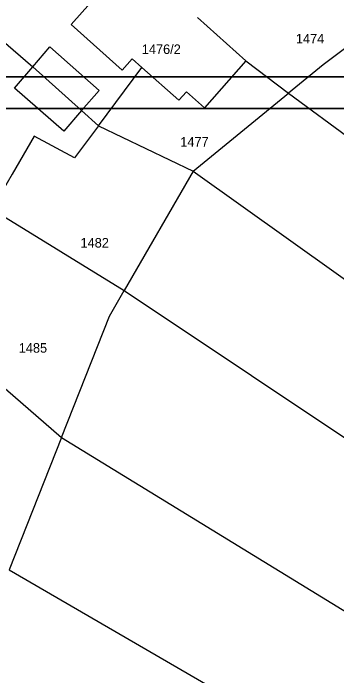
# Model space of a CAD drawing. Extents: x -601580 to 4, y -1204314 to 4.
# Drawn here: x -598853.3 to -598827.9, y -1203943.9 to -1203891.8 of the extents above; entities that cross this region are included whole.
import ezdxf

# ---------------------------------------------------------------- set-up
doc = ezdxf.new("R2010")
doc.units = 0
for name, color, linetype in [('00-KN-HRANICE PARCEL', 7, 'Continuous'), ('00-KN-PARC. CISLA', 7, 'Continuous'), ('00-KN-VNITRNI KRESBA', 7, 'Continuous'), ('00-RAZÍTKO', 7, 'Continuous')]:
    doc.layers.add(name, color=color, linetype=linetype)

msp = doc.modelspace()

# ---------------------------------------------------------------- linework, layer by layer
for points in [[(-598795.141, -1204045.311), (-598795.141, -1203896.811), (-599005.141, -1203896.811), (-599005.141, -1204045.311)], [(-598797.641, -1204042.811), (-598797.641, -1203899.311), (-599002.641, -1203899.311), (-599002.641, -1204042.811)]]:
    msp.add_lwpolyline(points, close=True)
for points in [[(-598900.191, -1204042.811), (-598900.191, -1204045.311), (-598795.141, -1204045.311), (-598795.141, -1203896.811), (-598900.191, -1203896.811), (-598900.191, -1203899.311)], [(-598897.691, -1204042.811), (-598797.641, -1204042.811), (-598797.641, -1203899.311), (-598897.691, -1203899.311)]]:
    msp.add_lwpolyline(points)
at = {"layer": '00-KN-HRANICE PARCEL'}
for p, q in [((-598838.811, -1203892.159), (-598835.011, -1203895.569)), ((-598835.011, -1203895.569), (-598831.661, -1203898.109)), ((-598846.611, -1203900.659), (-598843.191, -1203896.079)), ((-598839.141, -1203904.219), (-598831.661, -1203898.109)), ((-598831.661, -1203898.109), (-598778.841, -1203936.669)), ((-598846.611, -1203900.659), (-598839.141, -1203904.219)), ((-598839.141, -1203904.219), (-598844.571, -1203913.599)), ((-598854.991, -1203907.199), (-598844.571, -1203913.599)), ((-598859.991, -1203916.109), (-598849.501, -1203925.149)), ((-598849.501, -1203925.149), (-598853.621, -1203935.559))]:
    msp.add_line(p, q, dxfattribs=at)
for points in [[(-598863.941, -1203885.569), (-598856.251, -1203892.169), (-598851.771, -1203896.019)], [(-598843.191, -1203896.079), (-598843.941, -1203895.389), (-598844.731, -1203896.289), (-598848.761, -1203892.709), (-598846.571, -1203890.249), (-598847.351, -1203889.549), (-598844.901, -1203886.789)], [(-598825.061, -1203892.989), (-598828.931, -1203895.879), (-598831.661, -1203898.109)], [(-598835.011, -1203895.569), (-598838.261, -1203899.249), (-598839.681, -1203897.989), (-598840.281, -1203898.659), (-598843.191, -1203896.079)], [(-598851.771, -1203896.019), (-598847.931, -1203899.469), (-598846.611, -1203900.659)], [(-598846.611, -1203900.659), (-598848.501, -1203903.189), (-598851.671, -1203901.489)], [(-598851.671, -1203901.489), (-598853.401, -1203904.459), (-598854.991, -1203907.199)], [(-598839.141, -1203904.219), (-598786.271, -1203941.879), (-598785.311, -1203942.529)], [(-598849.501, -1203925.149), (-598845.741, -1203915.629), (-598844.571, -1203913.599)], [(-598844.571, -1203913.599), (-598794.321, -1203947.099), (-598792.031, -1203948.609)], [(-598849.501, -1203925.149), (-598803.711, -1203953.189), (-598789.701, -1203961.229)], [(-598853.621, -1203935.559), (-598812.931, -1203959.159), (-598806.131, -1203963.139)]]:
    msp.add_lwpolyline(points, dxfattribs=at)
at = {"layer": '00-KN-VNITRNI KRESBA'}
for p, q in [((-598851.771, -1203896.019), (-598850.431, -1203894.469)), ((-598850.431, -1203894.469), (-598846.561, -1203897.879)), ((-598853.221, -1203897.709), (-598851.771, -1203896.019)), ((-598849.331, -1203901.089), (-598853.221, -1203897.709)), ((-598846.561, -1203897.879), (-598847.931, -1203899.469)), ((-598847.931, -1203899.469), (-598849.331, -1203901.089))]:
    msp.add_line(p, q, dxfattribs=at)
at = {"layer": '00-RAZÍTKO'}
for points in [[(-599005.242, -1203896.811), (-598795.141, -1203896.811), (-598795.141, -1204045.311), (-599005.242, -1204045.311)], [(-599005.242, -1203899.311), (-598797.641, -1203899.311), (-598797.641, -1204042.811), (-599005.242, -1204042.811)]]:
    msp.add_lwpolyline(points, dxfattribs=at)

# ---------------------------------------------------------------- texts
at = {"layer": '00-KN-PARC. CISLA'}
for s, p in [('1474', (-598831.066, -1203894.189)), ('1476/2', (-598843.192, -1203895.019)), ('1477', (-598840.166, -1203902.299)), ('1482', (-598848.016, -1203910.229)), ('1485', (-598852.876, -1203918.489))]:
    msp.add_text(s, height=0.75, dxfattribs=at).set_placement(p)

doc.saveas('drawing.dxf')
